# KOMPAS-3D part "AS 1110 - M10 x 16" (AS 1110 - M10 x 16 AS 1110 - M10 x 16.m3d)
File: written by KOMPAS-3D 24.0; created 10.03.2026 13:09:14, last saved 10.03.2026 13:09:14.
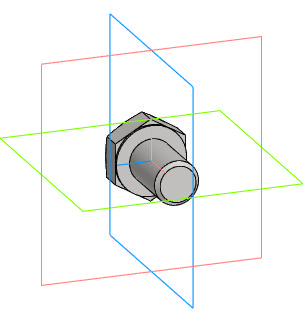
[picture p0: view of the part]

Document properties: Автор: R2D2; Полное имя файла: E:\Работа\Зайцев\BV3232P(4pc)-FP-3WL-F-ISO-H Кран шаровой DN.ru Ду15-100 Ру16\DN80\исходные материалы\AS 1110 - M10 x 16 AS 1110 - M10 x 16.m3d

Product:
- Body: Solid1  | qty 1
- Part/product: AS 1110 - M10 x 16
    Комментарий: Болты и винты   шестигранные точные   метрические ISO
    additional columns: Сталь, мягкая

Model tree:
1. Solid1  (labels: Solid1)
